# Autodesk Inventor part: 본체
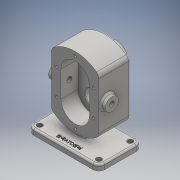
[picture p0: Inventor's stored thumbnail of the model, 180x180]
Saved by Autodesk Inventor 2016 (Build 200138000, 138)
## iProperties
Created: 2019-03
Part Number: 본체
Material: 일반
Document SubType Name: Modeling
Designer: USER
Density: 1 g/cm^3
Appearance: 기본값
Author: USER
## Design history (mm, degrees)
sketch "스케치1"
  geometry: L1 (0, 0)-(120, 0); L2 (120, 0)-(120, 73); L3 (120, 73)-(0, 73); L4 (0, 73)-(0, 0); 1 further point
  constraints: 8 end point, 2 perpendicular, 1 coincident, 1 horizontal
  dimensions: "d3" = 120 distance of L1.start L1.end; "d4" = 73 distance of L1.end L2.end; "d5" = 120 distance of L2.end L3.end
extrude "돌출1" new body sketch "스케치1" distance "d6" = 10; taper "d7" = 0 deg
fillet "모깎기1" dims "d8" = 10
sketch "스케치2"
  geometry: L1 (110, 73)-(10, 73) reference; L2 (0, 63)-(0, 10) reference; L3 (10, 0)-(110, 0) reference; L4 (120, 10)-(120, 63) reference; L5 (110, 73)-(10, 73) reference; C1 r 4.5 at (10, 63); C2 r 4.5 at (10, 10); C3 r 4.5 at (110, 63); C4 r 4.5 at (110, 10); A1 r 10 centre (10, 63) between (10, 73) and (0, 63) reference; A2 r 10 centre (10, 10) between (0, 10) and (10, 0) reference; A3 r 10 centre (110, 10) between (110, 0) and (120, 10) reference; A4 r 10 centre (110, 63) between (120, 63) and (110, 73) reference; 1 further point
  constraints: 4 centre point, 4 coincident
  dimensions: "d9" = 9 diameter of C1; "d10" = 9 diameter of C2; "d11" = 9 diameter of C3; "d12" = 9 diameter of C4
extrude "돌출2" cut sketch "스케치2" distance "d13" = 10; taper "d14" = 0 deg
node "작업 평면2"
sketch "스케치4"
  geometry: L1 (-10, 0)-(-110, 0) reference; L2 (-60, 0)-(-60, 78); L3 (-20, 33.279)-(-20, 122.721); L4 (-100, 33.279)-(-100, 122.721); A1 r 60 centre (-60, 78) between (-100, 33.279) and (-20, 33.279); A2 r 60 centre (-60, 78) between (-20, 122.721) and (-100, 122.721); 1 further point
  constraints: 6 end point, 4 point on circle, 2 centre point, 2 parallel, 1 coincident, 1 midpoint, 1 vertical
  dimensions: "d23" = 78 distance of L2.start L2.end; "d24" = 40 distance between parallel lines of L2 L3; "d25" = 40 distance between parallel lines of L2 L4; "d27" = 60 radius of A2; "d28" = 60 radius of A1
extrude "돌출3" join sketch "스케치4" distance "d29" = 53; taper "d30" = 0 deg
sketch "스케치5"
  geometry: L1 (20, 122.721)-(20, 33.279) reference; L2 (100, 33.279)-(100, 122.721) reference; L3 (20, 122.721)-(20, 33.279) reference; L4 (36, 78)-(84, 78); L5 (100, 33.279)-(100, 122.721) reference; L6 (60, 124)-(60, 32); L7 (36, 100)-(36, 56); L8 (84, 100)-(84, 56); A1 r 60 centre (60, 78) between (20, 33.279) and (100, 33.279) reference; A2 r 60 centre (60, 78) between (100, 122.721) and (20, 122.721) reference; A3 r 60 centre (60, 78) between (20, 33.279) and (100, 33.279) reference; A4 r 24 centre (60, 100) between (84, 100) and (36, 100); A5 r 24 centre (60, 56) between (36, 56) and (84, 56); 5 further points
  constraints: 8 end point, 7 midpoint, 7 point on circle, 3 horizontal alignment, 2 centre point, 2 point on line, 2 vertical alignment
  dimensions: "d36" = 24 radius of A5; "d37" = 44 distance of L7.start L7.end; "d38" = 44 distance of L8.start L8.end; "d39" = 16 distance between parallel lines of L1 L7; "d40" = 48 distance of L4.start L4.end; "d41" = 24 radius of A4
extrude "돌출4" cut sketch "스케치5" distance "d42" = 29; taper "d43" = 0 deg
sketch "스케치6"
  geometry: L1 (84, 100)-(84, 56) reference; L2 (36, 56)-(36, 100) reference; C1 r 12.5 at (60, 100); C2 r 12.5 at (60, 56); A1 r 24 centre (60, 100) between (84, 100) and (36, 100) reference; A2 r 24 centre (60, 56) between (36, 56) and (84, 56) reference; 1 further point
  constraints: 2 centre point, 2 coincident
  dimensions: "d44" = 25 diameter of C1; "d45" = 25 diameter of C2
extrude "돌출5" cut sketch "스케치6" distance "d46" = 15; taper "d47" = 0 deg
sketch "스케치8"
  geometry: L1 (20, -33.279)-(20, -122.721) reference; L2 (100, -122.721)-(100, -33.279) reference; L3 (60, -78)-(60, -100); C1 r 19 at (60, -100); A1 r 60 centre (60, -78) between (20, -122.721) and (100, -122.721) reference; A2 r 60 centre (60, -78) between (100, -33.279) and (20, -33.279) reference; 1 further point
  constraints: 2 end point, 1 centre point, 1 coincident, 1 vertical
  dimensions: "d48" = 22 distance of L3.start L3.end; "d49" = 38 diameter of C1
extrude "돌출6" join sketch "스케치8" distance "d50" = 17; taper "d51" = 0 deg
node "작업 평면3"
sketch "스케치10"
  geometry: L1 (64, 87.5)-(64, 112.5) reference; L2 (64, 100)-(90, 100); L3 (20, 100)-(49, 100) reference; L4 (64, 100)-(64, 108.5); L5 (90, 81)-(90, 119) reference; L6 (90, 100)-(90, 114); L7 (90, 114)-(82.7, 114); L8 (82.7, 114)-(82.7, 108.5); L9 (82.7, 108.5)-(64, 108.5); 1 further point
  constraints: 12 end point, 3 perpendicular, 2 midpoint, 2 point on line, 1 collinear
  dimensions: "d54" = 14 distance of L2.end L6.end; "d55" = 7.3 distance of L6.end L7.end; "d56" = 17 diameter of L9 L2
revolve "회전1" sketch "스케치10" stored, may be unused: angle "d57" = 90 deg
sketch "스케치11"
  geometry: L1 (10, 0)-(110, 0) reference; L2 (60, 0)-(60, 73); L3 (110, 73)-(10, 73) reference; L4 (54, 30)-(54, 73); L5 (66, 30)-(66, 73); L6 (54, 73)-(66, 73); L7 (66, 30)-(54, 30); 1 further point
  constraints: 10 end point, 3 parallel, 2 midpoint, 1 collinear
  dimensions: "d58" = 6 distance between parallel lines of L2 L4; "d59" = 6 distance between parallel lines of L2 L5; "d60" = 43 distance between parallel lines of L3 L7; "d62" = 43 distance of L5.start L5.end
extrude "돌출7" join sketch "스케치11" distance "d63" = 15; taper "d64" = 0 deg
sketch "스케치12"
  geometry: L1 (84, 100)-(84, 56) reference; L2 (36, 56)-(36, 100) reference; L3 (20, 122.721)-(20, 33.279) reference; L4 (100, 33.279)-(100, 122.721) reference; L5 (29, 100)-(29, 56); L6 (91, 100)-(91, 56); A1 r 24 centre (60, 100) between (84, 100) and (36, 100) reference; A2 r 24 centre (60, 56) between (36, 56) and (84, 56) reference; A3 r 60 centre (60, 78) between (20, 33.279) and (100, 33.279) reference; A4 r 60 centre (60, 78) between (100, 122.721) and (20, 122.721) reference; A5 r 31 centre (60, 56) between (29, 56) and (91, 56); A6 r 31 centre (60, 100) between (60, 131) and (29, 100); 6 further points
  constraints: 6 coincident, 6 point on circle, 4 end point, 4 tangent, 2 centre point, 2 vertical alignment
  dimensions: "d65" = 62 diameter of A5; "d66" = 62 diameter of A6
hole "구멍1" sketch "스케치12" at (60, 131), (29, 100), (91, 100), (91, 56), (29, 56), (60, 25) diameter "d67" = 4.134; stored, may be unused: countersink angle "d71" = 90 deg, drill point angle "d73" = 118 deg; dims "d68" = 10, "d69" = 4, "d70" = 2, "d72" = 12
sketch "스케치13"
  geometry: L1 (122.721, -10)-(122.721, -63) reference; L2 (89.443, -53)-(0, -53) reference; C1 r 11 at (44.721, -39); 1 further point
  constraints: 1 centre point
  dimensions: "d117" = 14 distance from line of L2 C1.centre; "d118" = 78 distance from line of L1 C1.centre; "d119" = 22 diameter of C1
extrude "돌출8" join sketch "스케치13" distance "d77" = 8; taper "d78" = 0 deg
sketch "스케치14"
  geometry: L1 (-33.279, -10)-(-33.279, -63) reference; L2 (89.443, -53)-(0, -53) reference; C1 r 11 at (44.721, -39); 1 further point
  constraints: 1 centre point
  dimensions: "d80" = 22 diameter of C1; "d120" = 14 distance from line of C1.centre L2; "d121" = 78 distance from line of L1 C1.centre
extrude "돌출9" join sketch "스케치14" distance "d81" = 8; taper "d82" = 0 deg
sketch "스케치15"
  geometry: C1 r 11 at (0, 0) reference; 2 further points
  constraints: 1 coincident
  node "투영된 루프8"
sketch "스케치16"
  geometry: C1 r 11 at (0, 0) reference; 2 further points
  constraints: 1 coincident
hole "구멍2" sketch "스케치16" at (0, 0) diameter "d83" = 8.376; stored, may be unused: countersink angle "d87" = 90 deg, drill point angle "d89" = 118 deg; dims "d84" = 29, "d85" = 4, "d86" = 2, "d88" = 30
hole "구멍3" sketch "스케치15" diameter "d90" = 8.376; stored, may be unused: countersink angle "d94" = 90 deg, drill point angle "d96" = 118 deg; dims "d91" = 29, "d92" = 4, "d93" = 2, "d95" = 30
node "작업 평면4"
sketch "스케치17"
  geometry: L1 (0, 63)-(0, 10) reference; L2 (10, 0)-(110, 0) reference; 2 further points
  constraints: 1 other
  dimensions: "d98" = 60 distance from line of L1 point (60, 10); "d99" = 10 distance from line of L2 point (60, 10)
feature "엠보싱1" sketch "스케치17" dims "d3" = 120, "d4" = 73, "d5" = 120, "d100" = 0.5, "d101" = 0
fillet "모깎기2" dims "d102" = 3
fillet "모깎기3" dims "d103" = 10
fillet "모깎기4" dims "d104" = 3
fillet "모깎기5" dims "d105" = 3
fillet "모깎기6" dims "d106" = 3
fillet "모깎기7" dims "d107" = 3
chamfer "모따기1" distance "d108" = 1; stored, may be unused: second distance "d109" = 2, angle "d110" = 45 deg
fillet "모깎기8" dims "d111" = 3
chamfer "모따기2" distance "d112" = 0.7; stored, may be unused: second distance "d113" = 2, angle "d114" = 30 deg
fillet "모깎기9" dims "d115" = 0.5
fillet "모깎기10" dims "d116" = 3
node "솔리드1"
node "투영된 루프1"
node "투영된 루프2"
node "투영된 루프3"
node "투영된 루프5"
node "투영된 루프7"
node "투영된 루프9"
other parameters: "d22" = 73, "d33" = 48, "d34" = 48
